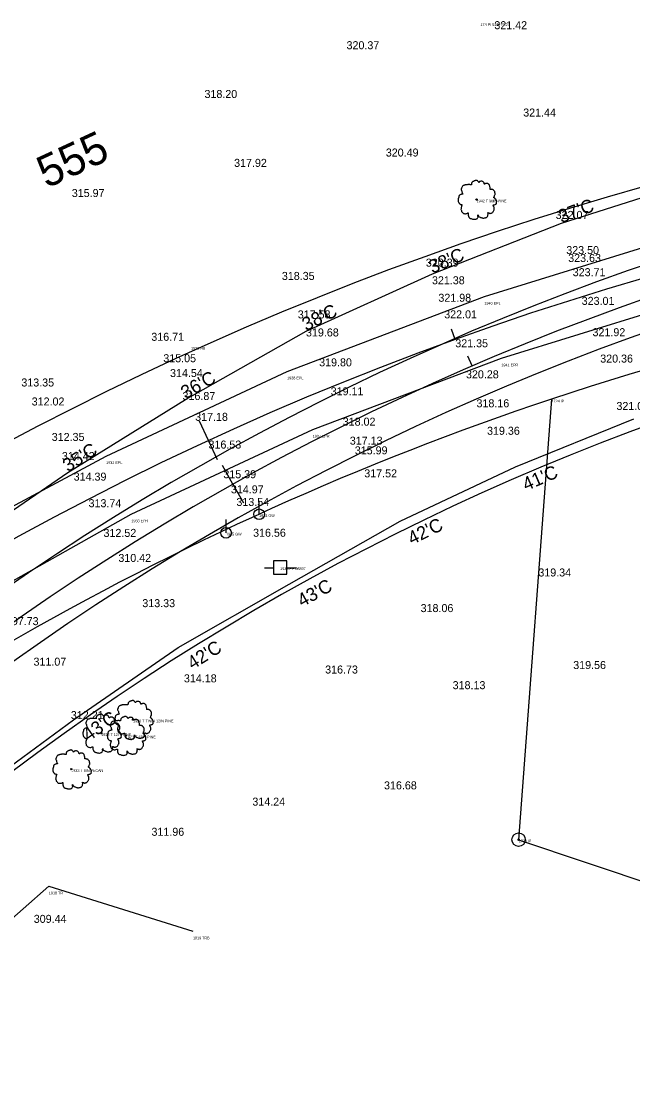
# Model space of a CAD drawing. Extents: x 49683 to 58852, y 49525 to 54803.
# Drawn here: x 56240.8 to 56470.1, y 53727.3 to 54122.5 of the extents above; entities that cross this region are included whole.
import ezdxf

# ---------------------------------------------------------------- set-up
doc = ezdxf.new("R2010")
doc.units = 0
for name, color, linetype in [('Level 1', 7, 'Continuous'), ('Level 11', 7, 'Continuous'), ('Level 12', 7, 'Continuous'), ('Level 13', 7, 'Continuous'), ('Level 18', 7, 'Continuous'), ('Level 19', 7, 'Continuous'), ('Level 20', 7, 'Continuous'), ('Level 21', 7, 'Continuous'), ('Level 3', 7, 'Continuous'), ('Level 32', 7, 'Continuous'), ('Level 33', 7, 'Continuous'), ('Level 48', 7, 'Continuous'), ('Level 51', 7, 'Continuous'), ('Level 53', 7, 'Continuous'), ('Level 59', 7, 'Continuous'), ('Level 61', 7, 'Continuous'), ('Level 62', 7, 'Continuous'), ('Level 9', 7, 'Continuous')]:
    doc.layers.add(name, color=color, linetype=linetype)

# ---------------------------------------------------------------- blocks, each defined once
blk = doc.blocks.new('IP')
at = {"layer": 'Level 12'}
for radius in [2.5, 0.25]:
    blk.add_circle((0, 0), radius, dxfattribs=at)
blk = doc.blocks.new('T1')
at = {"layer": 'Level 11'}
for centre, radius in [((0, 0), 0.25), ((-0.01, -0.02), 0.0001)]:
    blk.add_circle(centre, radius, dxfattribs=at)
for points in [[(0.13, 7.17), (-0.17, 7.19), (-0.49, 7.09), (-0.74, 6.99), (-0.97, 6.92), (-1.19, 6.82), (-1.49, 6.64), (-1.72, 6.44), (-1.84, 6.19), (-1.89, 5.97), (-1.94, 5.69), (-1.94, 5.52), (-2.07, 5.49), (-2.22, 5.52), (-2.47, 5.59), (-2.72, 5.59), (-2.97, 5.59), (-3.32, 5.57), (-3.67, 5.57), (-3.94, 5.52), (-4.27, 5.47), (-4.64, 5.34), (-4.99, 5.22), (-5.29, 4.97), (-5.54, 4.49), (-5.67, 4.14), (-5.82, 3.89), (-5.67, 3.44), (-5.49, 3.09), (-5.47, 2.89), (-5.39, 2.47), (-5.29, 2.24), (-5.17, 2.04), (-5.24, 2.02), (-5.62, 1.97), (-5.92, 1.87), (-6.34, 1.64), (-6.57, 1.42), (-6.67, 1.09), (-6.69, 0.75), (-6.79, 0.55), (-6.87, 0.27), (-6.89, 0.2), (-6.94, -0.13), (-6.84, -0.58), (-6.82, -0.93), (-6.69, -1.15), (-6.54, -1.33), (-6.37, -1.58), (-5.97, -1.8), (-5.64, -1.9), (-5.44, -1.93), (-5.62, -2.43), (-5.67, -2.78), (-5.79, -3.18), (-5.79, -3.25), (-5.84, -3.73), (-5.69, -4.05), (-5.62, -4.43), (-5.44, -4.65), (-5.17, -4.95), (-4.84, -5.18), (-4.34, -5.3), (-3.94, -5.28), (-3.37, -5.1), (-3.12, -5.03), (-3.14, -5.2), (-3.12, -5.58), (-3.12, -6), (-2.97, -6.33), (-2.87, -6.6), (-2.72, -6.85), (-2.39, -7.08), (-1.99, -7.15), (-1.57, -7.3), (-1.12, -7.38), (-0.62, -7.4), (-0.02, -7.25), (0.26, -7.13), (0.36, -6.95), (0.56, -6.58), (0.51, -6.35), (0.53, -5.75), (0.63, -5.93), (0.81, -6.28), (1.31, -6.58), (1.71, -6.75), (2.18, -6.9), (2.48, -6.98), (2.96, -6.9), (3.33, -6.83), (3.71, -6.7), (4.01, -6.43), (4.18, -6.15), (4.23, -5.88), (4.31, -5.5), (4.36, -5.33)], [(4.36, -5.33), (4.28, -5.15), (4.23, -4.9), (4.31, -4.93), (4.48, -4.98), (4.75, -5.1), (4.98, -5.18), (5.3, -5.15), (5.58, -5.05), (6.03, -4.78), (6.3, -4.3), (6.58, -3.9), (6.65, -3.58), (6.6, -3.35), (6.58, -2.85), (6.38, -2.6), (6.33, -2.48), (6.23, -2.08), (6.3, -2.03), (6.58, -1.98), (6.95, -1.85), (7.23, -1.73), (7.45, -1.55), (7.53, -1.33), (7.5, -0.93), (7.55, -0.53), (7.48, -0.38), (7.38, -0.23), (7.3, -0.03), (7.15, 0.12), (7.05, 0.27), (6.95, 0.37), (6.83, 0.52), (6.65, 0.65), (6.5, 0.7), (6.45, 0.85), (6.6, 1.04), (6.65, 1.14), (6.68, 1.37), (6.9, 1.72), (6.95, 2.12), (6.9, 2.54), (6.85, 2.82), (6.7, 3.09), (6.5, 3.34), (6.38, 3.52), (6.2, 3.64), (5.88, 3.77), (5.63, 3.82), (5.28, 3.82), (5.08, 3.87), (5.1, 3.92), (5.1, 4.07), (5.1, 4.34), (5.03, 4.79), (4.88, 5.29), (4.88, 5.32), (4.78, 5.57), (4.56, 5.77), (4.38, 5.87), (4.18, 5.99), (3.93, 6.02), (3.63, 6.02), (3.36, 5.97), (3.16, 5.87), (2.98, 5.74), (2.91, 5.89), (2.81, 6.19), (2.76, 6.34), (2.61, 6.52), (2.38, 6.72), (1.93, 6.84), (1.31, 6.77), (1.01, 6.57), (0.86, 6.39), (0.81, 6.52), (0.61, 6.72), (0.51, 6.89), (0.33, 7.02), (0.18, 7.12), (0.08, 7.17)]]:
    blk.add_spline(points, degree=3, dxfattribs=at)
blk = doc.blocks.new('GW')
at = {"layer": 'Level 9'}
blk.add_line((0, 0), (0, 5), dxfattribs=at)
blk.add_circle((0, 0), 2, dxfattribs=at)
blk = doc.blocks.new('PP')
at = {"layer": 'Level 9'}
for p, q in [((2.53, 2.45), (-2.47, 2.45)), ((-2.47, 2.45), (-2.47, -2.55)), ((2.53, -2.55), (2.53, 2.45)), ((-5.91, -0.11), (-2.44, -0.11)), ((-2.47, -2.55), (2.53, -2.55)), ((2.45, -0.11), (6.09, -0.11))]:
    blk.add_line(p, q, dxfattribs=at)

msp = doc.modelspace()

# ---------------------------------------------------------------- linework, layer by layer
at = {"layer": 'Level 1'}
for p, q in [((56403.49, 54003.28), (56402.13, 54007.04)), ((56311, 53965.34), (56307.64, 53972.6)), ((56314.36, 53958.08), (56311, 53965.34))]:
    msp.add_line(p, q, dxfattribs=at)
msp.add_arc((56791.72, 52925.13), 1145.92, 83.49443, 131.63333, dxfattribs=at)
at = {"layer": 'Level 11'}
for p, q in [((56218.32, 53769.53), (56251.21, 53798.33)), ((56251.21, 53798.33), (56305.22, 53781.48))]:
    msp.add_line(p, q, dxfattribs=at)
at = {"layer": 'Level 12'}
for p, q in [((56439.6, 53980.87), (56427.28, 53815.81)), ((56427.28, 53815.81), (56690.99, 53727.29))]:
    msp.add_line(p, q, dxfattribs=at)
at = {"layer": 'Level 13'}
for radius, start, end in [(1178.92, 86.60044, 131.63335), (1112.92, 83.49442, 108.44495), (1112.92, 108.44495, 131.63335)]:
    msp.add_arc((56791.72, 52925.13), radius, start, end, dxfattribs=at)
at = {"layer": 'Level 18'}
for p, q in [((56443.3, 54046.77), (56492.76, 54062.49)), ((56394.94, 54027.84), (56443.3, 54046.77)), ((56347.65, 54006.31), (56394.94, 54027.84)), ((56302.44, 53980.75), (56347.65, 54006.31)), ((56258.38, 53953.39), (56302.44, 53980.75)), ((56426.1, 53955.57), (56470.5, 53973.46)), ((56215.63, 53924.12), (56258.38, 53953.39)), ((56382.84, 53935.11), (56426.1, 53955.57)), ((56341.23, 53911.53), (56382.84, 53935.11)), ((56299.73, 53887.82), (56341.23, 53911.53)), ((56260.4, 53860.66), (56299.73, 53887.82)), ((56221.89, 53832.37), (56260.4, 53860.66))]:
    msp.add_line(p, q, dxfattribs=at)
at = {"layer": 'Level 19'}
for p, q in [((56409.83, 53993.31), (56408.24, 53996.98)), ((56320.22, 53949.03), (56316.31, 53956.01)), ((56320.22, 53949.03), (56324.13, 53942.05))]:
    msp.add_line(p, q, dxfattribs=at)
msp.add_arc((56791.96, 53107.19), 965, 83.49443, 131.63337, dxfattribs=at)
at = {"layer": 'Level 20'}
for radius, start, end in [(977, 84.11358, 131.63331), (953, 83.49443, 131.63337)]:
    msp.add_arc((56791.96, 53107.19), radius, start, end, dxfattribs=at)
at = {"layer": 'Level 3'}
for p, q in [((56414.45, 54019.29), (56490.09, 54042.73)), ((56420.81, 53996.17), (56497.78, 54020.06)), ((56340.54, 53991.29), (56414.45, 54019.29)), ((56350.09, 53969.49), (56420.81, 53996.17)), ((56272.68, 53959.54), (56340.54, 53991.29)), ((56282.12, 53937.76), (56350.09, 53969.49)), ((56206.74, 53924.16), (56272.68, 53959.54)), ((56207.19, 53895.72), (56282.12, 53937.76))]:
    msp.add_line(p, q, dxfattribs=at)
at = {"layer": 'Level 33'}
msp.add_arc((56791.96, 53107.19), 920, 83.49443, 131.63337, dxfattribs=at)

# ---------------------------------------------------------------- block references
at = {"layer": 'Level 11'}
for p in [(56411.51, 54055.66), (56282.78, 53860.79), (56270.85, 53855.68), (56280.04, 53854.81), (56259.6, 53842.22)]:
    msp.add_blockref('T1', p, dxfattribs=at)
at = {"layer": 'Level 12'}
msp.add_blockref('IP', (56427.28, 53815.81), dxfattribs=at)
at = {"layer": 'Level 9'}
for name, p in [('GW', (56330.04, 53937.74)), ('GW', (56317.61, 53930.78)), ('PP', (56337.92, 53917.82))]:
    msp.add_blockref(name, p, dxfattribs=at)

# ---------------------------------------------------------------- texts
at = {"layer": 'Level 21'}
msp.add_text('555', height=12, rotation=24.8036, dxfattribs=at).set_placement((56250.36, 54059.71))
at = {"layer": 'Level 32'}
for s, p in [('321.42', (56418.18, 54119.48)), ('320.37', (56362.78, 54111.98)), ('318.20', (56309.54, 54093.71)), ('321.44', (56429, 54086.76)), ('320.49', (56377.49, 54071.78)), ('317.92', (56320.64, 54067.9)), ('315.97', (56259.81, 54056.6)), ('322.07', (56441.15, 54048.39)), ('323.50', (56445.13, 54035.22)), ('320.39', (56392.5, 54030.52)), ('323.63', (56445.85, 54032.26)), ('318.35', (56338.54, 54025.54)), ('323.71', (56447.55, 54026.94)), ('321.38', (56394.79, 54023.91)), ('321.98', (56397.2, 54017.36)), ('323.01', (56450.91, 54016.19)), ('317.58', (56344.5, 54011.12)), ('322.01', (56399.39, 54011.14)), ('316.71', (56289.61, 54002.73)), ('319.68', (56347.59, 54004.36)), ('321.92', (56454.97, 54004.45)), ('321.35', (56403.53, 54000.3)), ('315.05', (56294.1, 53994.7)), ('319.80', (56352.52, 53993.16)), ('320.36', (56457.86, 53994.57)), ('314.54', (56296.62, 53989.15)), ('313.35', (56240.9, 53985.61)), ('320.28', (56407.55, 53988.66)), ('319.11', (56356.83, 53982.32)), ('312.02', (56244.78, 53978.49)), ('316.87', (56301.31, 53980.55)), ('318.16', (56411.49, 53977.82)), ('321.02', (56463.93, 53976.82)), ('317.18', (56306.05, 53972.74)), ('318.02', (56361.35, 53970.93)), ('319.36', (56415.44, 53967.52)), ('312.35', (56252.29, 53965.21)), ('316.53', (56311.05, 53962.35)), ('317.13', (56364, 53963.82)), ('314.42', (56256.1, 53958.05)), ('315.99', (56365.87, 53960.19)), ('314.39', (56260.51, 53950.34)), ('315.39', (56316.61, 53951.24)), ('317.52', (56369.43, 53951.56)), ('314.97', (56319.45, 53945.57)), ('313.74', (56266.09, 53940.38)), ('313.54', (56321.5, 53940.85)), ('312.52', (56271.69, 53929.25)), ('316.56', (56327.75, 53929.31)), ('310.42', (56277.27, 53919.87)), ('319.34', (56434.67, 53914.43)), ('313.33', (56286.24, 53902.93)), ('318.06', (56390.54, 53901.08)), ('307.73', (56235.09, 53896.19)), ('311.07', (56245.46, 53881)), ('319.56', (56447.74, 53879.74)), ('314.18', (56301.83, 53874.75)), ('316.73', (56354.77, 53878.06)), ('318.13', (56402.55, 53872.2)), ('312.21', (56259.45, 53860.99)), ('316.68', (56376.83, 53834.65)), ('314.24', (56327.48, 53828.56)), ('311.96', (56289.67, 53817.27)), ('309.44', (56245.55, 53784.64))]:
    msp.add_text(s, height=3, dxfattribs=at).set_placement(p)
at = {"layer": 'Level 48'}
for s, rotation, p in [("37'C", 20.3591, (56443.3, 54046.77)), ("38'C", 23.3278, (56394.94, 54027.84)), ("38'C", 26.2965, (56347.65, 54006.31)), ("36'C", 29.2652, (56302.44, 53980.75)), ("35'C", 32.2339, (56258.38, 53953.39)), ("41'C", 23.3278, (56430.06, 53946.39)), ("42'C", 26.2965, (56387.27, 53926.14)), ("43'C", 29.2652, (56346.12, 53902.81)), ("42'C", 32.2339, (56305.06, 53879.36)), ("43'C", 35.2026, (56266.16, 53852.49))]:
    msp.add_text(s, height=5, rotation=rotation, dxfattribs=at).set_placement(p)
at = {"layer": 'Level 51'}
msp.add_text('174 PI 556+75.27 ', height=1, dxfattribs=at).set_placement((56412.99, 54120.66))
at = {"layer": 'Level 53'}
for s, p in [('1940 EPL ', (56414.45, 54016.29)), ('1941 EPR ', (56420.81, 53993.17)), ('1938 EPL ', (56340.54, 53988.29)), ('1937 EPR ', (56350.09, 53966.49)), ('1932 EPL ', (56272.68, 53956.54)), ('1933 EPR ', (56282.12, 53934.76))]:
    msp.add_text(s, height=1, dxfattribs=at).set_placement(p)
at = {"layer": 'Level 59'}
for s, p in [('1934 GW ', (56330.04, 53936.74)), ('1935 GW ', (56317.61, 53929.78)), ('1936 PP 08897 ', (56337.92, 53916.82))]:
    msp.add_text(s, height=1, dxfattribs=at).set_placement(p)
at = {"layer": 'Level 61'}
for s, p in [('1942 T 36IN PINE ', (56411.51, 54054.66)), ('1939 HB ', (56304.49, 53999.43)), ('1920 T TWIN 12IN PINE ', (56282.78, 53859.79)), ('1922 T 12IN PINE ', (56270.85, 53854.68)), ('1921 T 12IN PINE ', (56280.04, 53853.81)), ('1923 T 8IN PECAN ', (56259.6, 53841.22)), ('1918 TR ', (56251.21, 53795.33)), ('1919 TRB ', (56305.22, 53778.48))]:
    msp.add_text(s, height=1, dxfattribs=at).set_placement(p)
at = {"layer": 'Level 62'}
for s, p in [('1724 IP ', (56439.58, 53979.62)), ('1723 IP ', (56427.28, 53814.81))]:
    msp.add_text(s, height=1, dxfattribs=at).set_placement(p)

doc.saveas('drawing.dxf')
